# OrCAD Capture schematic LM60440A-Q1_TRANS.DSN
size E; title: LM60440A-Q1 3.8-V to 36-V, 4-A Ultra-Small Synchronous; rev: 1.0; note: Datasheet:SNVSBO0     EVM:SNVU693; note: Synchronous Step Down Converter
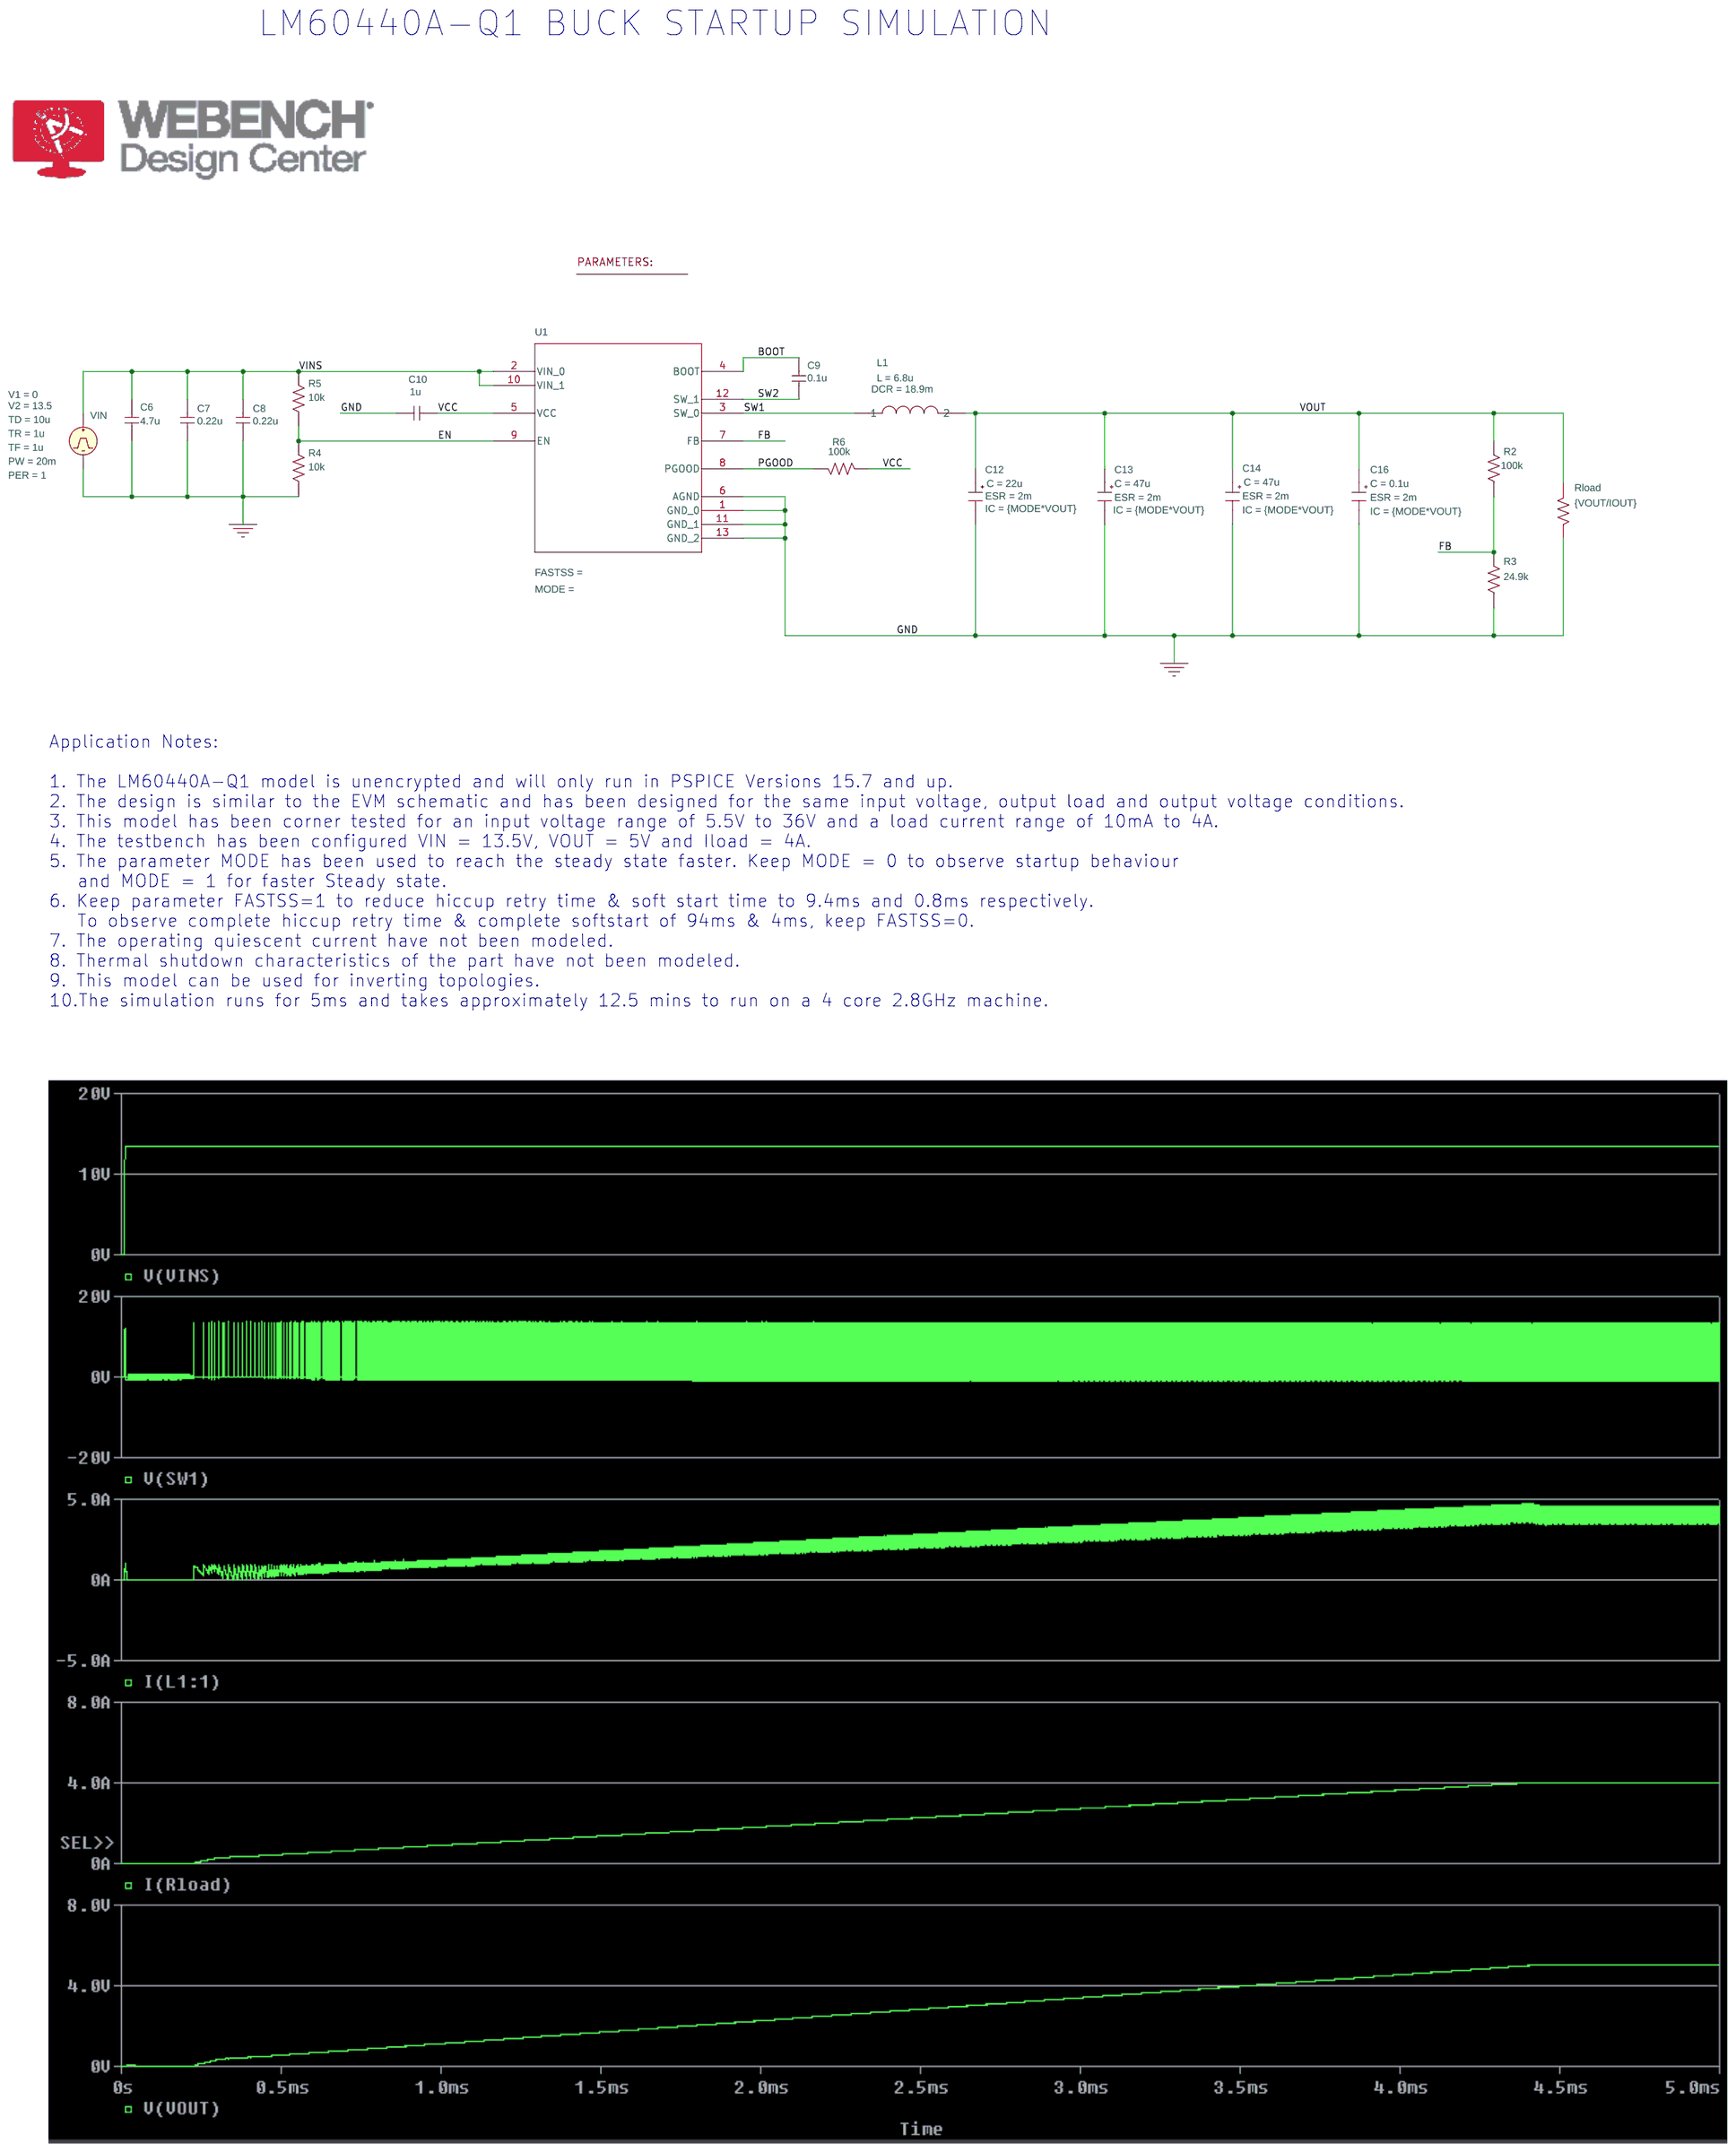
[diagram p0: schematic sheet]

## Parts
1  PARAM
C6  4.7u  [RAD/CK05]
C7  0.22u  [RAD/CK05]
C8  0.22u  [RAD/CK05]
C9  0.1u  [RAD/CK05]
C10  1u  [RAD/CK05]
C12  CESR
C13  CESR
C14  CESR
C16  CESR
L1  LDCR
R2  100k  [AX/RC05]
R3  24.9k  [AX/RC05]
R4  10k  [AX/RC05]
R5  10k  [AX/RC05]
R6  100k  [AX/RC05]
Rload  {VOUT/IOUT}  [AX/RC05]
U1  LM60440AQRPKRQ1  [RPK0013A-MFG]
VIN  VPULSE

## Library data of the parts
1 = PARAM: FASTSS: 0; IOUT: 4; MODE: 0; VIN: 13.5; VOUT: 5
C6-C10 = C
C12 = CESR_0: C: 22u; ESR: 2m; IC: {MODE*VOUT}; PSpiceTemplate: X^@REFDES %IN %OUT @MODEL PARAMS:  ?C|C=@C||C=100u|  ?ESR|ESR=@ESR||ESR=0.01| ?X|X=@X||X=2|  ?IC|IC=@IC||IC=2|; X: 1
C13 C14 = CESR_0: C: 47u; ESR: 2m; IC: {MODE*VOUT}; PSpiceTemplate: X^@REFDES %IN %OUT @MODEL PARAMS:  ?C|C=@C||C=100u|  ?ESR|ESR=@ESR||ESR=0.01| ?X|X=@X||X=2|  ?IC|IC=@IC||IC=2|; X: 1
C16 = CESR_0: C: 0.1u; ESR: 2m; IC: {MODE*VOUT}; PSpiceTemplate: X^@REFDES %IN %OUT @MODEL PARAMS:  ?C|C=@C||C=100u|  ?ESR|ESR=@ESR||ESR=0.01| ?X|X=@X||X=2|  ?IC|IC=@IC||IC=2|; X: 1
L1 = LDCR: DCR: 18.9m; L: 6.8u
R2-R6 Rload = R
U1 = LM60440A-Q1RPK_TRANS
VIN = VPULSE: PER: 1; PW: 20m; TD: 10u; TF: 1u; TR: 1u; V1: 0; V2: 13.5

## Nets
VCC: C10.1 R6.2 U1.5(VCC)
VINS: C6.2 C7.2 C8.2 R5.2 U1.2(VIN_0) U1.10(VIN_1) VIN.1(+)
0: C6.1 C7.1 C8.1 C10.2 C12.2(OUT) C13.2(OUT) C14.2(OUT) C16.2(OUT) R3.1 R4.1 Rload.2 U1.1(GND_0) U1.6(AGND) U1.11(GND_1) U1.13(GND_2) VIN.2(-)
BOOT: C9.2 U1.4(BOOT)
EN: R4.2 R5.1 U1.9(EN)
FB: R2.1 R3.2 U1.7(FB)
PGOOD: R6.1 U1.8(PGOOD)
SW1: L1.1 U1.3(SW_0)
SW2: C9.1 U1.12(SW_1)
VOUT: C12.1(IN) C13.1(IN) C14.1(IN) C16.1(IN) L1.2 R2.2 Rload.1

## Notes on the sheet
- LM60440A-Q1 BUCK STARTUP SIMULATION
- Application Notes:
  1. The LM60440A-Q1 model is unencrypted and will only run in PSPICE Versions 15.7 and up.
  2. The design is similar to the EVM schematic and has been designed for the same input voltage, output load and output voltage conditions.
  3. This model has been corner tested for an input voltage range of 5.5V to 36V and a load current range of 10mA to 4A.
  4. The testbench has been configured VIN = 13.5V, VOUT = 5V and Iload = 4A.
  5. The parameter MODE has been used to reach the steady state faster. Keep MODE = 0 to observe startup behaviour
     and MODE = 1 for faster Steady state.
  6. Keep parameter FASTSS=1 to reduce hiccup retry time & soft start time to 9.4ms and 0.8ms respectively.
     To observe complete hiccup retry time & complete softstart of 94ms & 4ms, keep FASTSS=0.
  7. The operating quiescent current have not been modeled.
  8. Thermal shutdown characteristics of the part have not been modeled.
  9. This model can be used for inverting topologies.
  10.The simulation runs for 5ms and takes approximately 12.5 mins to run on a 4 core 2.8GHz machine.
